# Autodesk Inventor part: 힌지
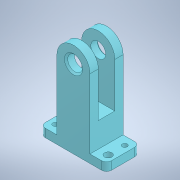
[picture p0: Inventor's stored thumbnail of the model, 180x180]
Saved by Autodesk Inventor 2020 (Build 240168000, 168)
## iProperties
Created: 2024-04
Part Number: 힌지
Material: 알루미늄 6061
Document SubType Name: Modeling
Designer: oem
Density: 2.71 g/cm^3
Appearance: 기본값
Author: jhkim
Sending System: Autodesk Inventor 2025
Preprocessor: ST-DEVELOPER v20
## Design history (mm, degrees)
feature "솔리드1"
node "솔리드2"
